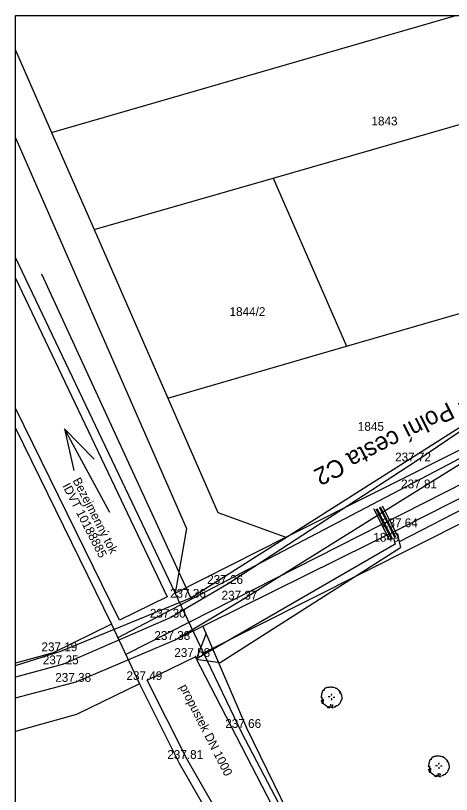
# Model space of a CAD drawing. Extents: x -601589 to -601440, y -1201842 to -1201527.
# Drawn here: x -601588.9 to -601539.2, y -1201615.4 to -1201526.7 of the extents above; entities that cross this region are included whole.
import ezdxf

# ---------------------------------------------------------------- set-up
doc = ezdxf.new("R2010")
doc.units = 0
for name, color, linetype in [('Definiční body', 7, 'Continuous'), ('Hranice parcel', 7, 'Continuous'), ('u_hrany', 7, 'Continuous'), ('u_osa', 7, 'Continuous'), ('u_popis', 7, 'Continuous'), ('u_příčný odvodňovací žlab', 7, 'Continuous'), ('u_terénní úpravy', 7, 'Continuous'), ('u_vysadba', 7, 'Continuous'), ('u_vyska', 7, 'Continuous'), ('x_rám', 7, 'Continuous')]:
    doc.layers.add(name, color=color, linetype=linetype)

msp = doc.modelspace()

# ---------------------------------------------------------------- linework, layer by layer
at = {"layer": 'Hranice parcel'}
for p, q in [((-601584.77, -1201539.96), (-601538.652, -1201526.653)), ((-601588.867, -1201530.599), (-601584.77, -1201539.96)), ((-601559.51, -1201545.16), (-601511.83, -1201531.46)), ((-601584.77, -1201539.96), (-601579.92, -1201551.03)), ((-601579.92, -1201551.03), (-601559.51, -1201545.16)), ((-601559.51, -1201545.16), (-601551.13, -1201564.33)), ((-601579.92, -1201551.03), (-601571.52, -1201570.23)), ((-601551.13, -1201564.33), (-601514.42, -1201553.71)), ((-601571.52, -1201570.23), (-601551.13, -1201564.33)), ((-601558.04, -1201586.08), (-601519.33, -1201566.6)), ((-601567.44, -1201599.25), (-601518.5, -1201574.62)), ((-601570.68, -1201592.44), (-601558.04, -1201586.08)), ((-601567.44, -1201599.25), (-601570.68, -1201592.44)), ((-601577.91, -1201595.98), (-601574.75, -1201602.78))]:
    msp.add_line(p, q, dxfattribs=at)
for points in [[(-601588.867, -1201540.58), (-601569.38, -1201585.08), (-601570.68, -1201592.44)], [(-601588.867, -1201554.262), (-601570.68, -1201592.44)], [(-601571.52, -1201570.23), (-601565.81, -1201583.28), (-601558.04, -1201586.08)], [(-601588.867, -1201573.638), (-601577.91, -1201595.98)], [(-601577.91, -1201595.98), (-601584.57, -1201599.24), (-601588.867, -1201600.418)], [(-601445.87, -1201723.83), (-601456.99, -1201723.59), (-601475.22, -1201720.69), (-601492.39, -1201715.61), (-601519.73, -1201684.8), (-601540.64, -1201651.14), (-601563.05, -1201608.38), (-601567.44, -1201599.25)], [(-601574.75, -1201602.78), (-601581.91, -1201606.29), (-601588.867, -1201608.194)], [(-601574.75, -1201602.78), (-601570.23, -1201611.8), (-601545.97, -1201654.03), (-601525.15, -1201688.8), (-601494.52, -1201722.78), (-601477.14, -1201727.24), (-601457.13, -1201731.39), (-601443.02, -1201731.69)]]:
    msp.add_lwpolyline(points, dxfattribs=at)
at = {"layer": 'u_hrany'}
for points in [[(-601517.05, -1201548.75), (-601518.98, -1201555.47), (-601521.95, -1201561.09), (-601526.18, -1201565.91), (-601543.22, -1201577.44), (-601564.63, -1201591.39), (-601571.15, -1201595.24), (-601583.39, -1201600.55), (-601588.867, -1201602.038)], [(-601568.87, -1201592.97), (-601585.89, -1201556.1)], [(-601588.867, -1201556.581), (-601571.58, -1201592.88), (-601577.01, -1201595.54), (-601588.867, -1201571.369)], [(-601583.7, -1201599.06), (-601568.87, -1201592.97), (-601526.18, -1201565.91)], [(-601588.867, -1201604.38), (-601581.97, -1201602.55), (-601570.67, -1201597.77), (-601563.01, -1201593.18), (-601542.69, -1201580.51), (-601524.37, -1201569.19), (-601517.89, -1201568.67), (-601514.2, -1201569.51), (-601511.31, -1201571.5), (-601509.75, -1201574.25)], [(-601570.67, -1201597.77), (-601544.7, -1201584.94), (-601517.03, -1201570.93)], [(-601567.51, -1201596.21), (-601562.55, -1201607.8), (-601549.33, -1201634.79), (-601540.29, -1201651.32), (-601519.62, -1201684.67)], [(-601588.867, -1201600.696), (-601583.7, -1201599.06)], [(-601573.85, -1201602.35), (-601568.4, -1201599.72), (-601541.51, -1201651.64)], [(-601545.11, -1201653.52), (-601569.35, -1201611.33), (-601573.85, -1201602.35)]]:
    msp.add_lwpolyline(points, dxfattribs=at)
at = {"layer": 'u_osa'}
msp.add_lwpolyline([(-601507.711, -1201526.653), (-601508.035, -1201556.382), (-601508.399, -1201559.4), (-601509.407, -1201562.268), (-601511.012, -1201564.849), (-601513.137, -1201567.023), (-601515.682, -1201568.685), (-601576.299, -1201599.446)], dxfattribs=at)
at = {"layer": 'u_popis'}
for p, q in [((-601578.133, -1201583.258), (-601583.273, -1201573.742)), ((-601583.273, -1201573.742), (-601582.207, -1201578.481)), ((-601583.273, -1201573.742), (-601579.913, -1201577.198))]:
    msp.add_line(p, q, dxfattribs=at)
at = {"layer": 'u_příčný odvodňovací žlab'}
for points in [[(-601545.609, -1201586.118), (-601546.515, -1201584.332), (-601547.353, -1201582.682)], [(-601545.52, -1201586.073), (-601546.426, -1201584.287), (-601547.263, -1201582.637)], [(-601545.297, -1201585.959), (-601546.203, -1201584.174), (-601547.041, -1201582.524)], [(-601546.216, -1201586.425), (-601547.122, -1201584.64), (-601548.027, -1201582.856)], [(-601545.993, -1201586.312), (-601546.899, -1201584.527), (-601547.736, -1201582.877)], [(-601545.904, -1201586.267), (-601546.81, -1201584.481), (-601547.647, -1201582.832)]]:
    msp.add_lwpolyline(points, dxfattribs=at)
at = {"layer": 'u_terénní úpravy'}
for p, q in [((-601545.756, -1201586.192), (-601545.593, -1201586.88)), ((-601545.297, -1201585.959), (-601544.993, -1201587.238)), ((-601567.152, -1201597.047), (-601568.274, -1201599.963)), ((-601568.271, -1201599.969), (-601565.539, -1201600.34))]:
    msp.add_line(p, q, dxfattribs=at)
for points in [[(-601511.197, -1201526.653), (-601511.285, -1201528.955), (-601511.232, -1201535.024), (-601513.147, -1201556.002), (-601514.131, -1201558.519), (-601515.245, -1201561.131), (-601516.655, -1201563.291), (-601517.726, -1201564.657), (-601519.33, -1201566.6), (-601521.678, -1201567.781), (-601538.799, -1201577.408), (-601577.284, -1201597.587)], [(-601510.358, -1201585.479), (-601510.939, -1201583.156), (-601511.905, -1201580.866), (-601513.234, -1201579.022), (-601515.173, -1201577.212), (-601516.815, -1201576.086), (-601517.621, -1201575.775), (-601519.795, -1201575.475), (-601521.737, -1201575.568), (-601523.807, -1201575.966), (-601536.406, -1201582.122), (-601545.145, -1201586.599)], [(-601545.593, -1201586.88), (-601568.271, -1201599.969)], [(-601565.539, -1201600.34), (-601544.993, -1201587.238)]]:
    msp.add_lwpolyline(points, dxfattribs=at)
at = {"layer": 'u_vysadba'}
for points in [[(-601553.83, -1201603.573), (-601553.829, -1201603.544), (-601553.769, -1201603.518), (-601553.739, -1201603.505), (-601553.709, -1201603.492), (-601553.679, -1201603.494), (-601553.65, -1201603.495), (-601553.663, -1201603.465), (-601553.676, -1201603.435), (-601553.659, -1201603.392), (-601553.643, -1201603.349), (-601553.611, -1201603.307), (-601553.58, -1201603.279), (-601553.55, -1201603.251), (-601553.504, -1201603.225), (-601553.46, -1201603.227), (-601553.43, -1201603.199), (-601553.355, -1201603.174), (-601553.296, -1201603.162), (-601553.251, -1201603.15), (-601553.193, -1201603.153), (-601553.148, -1201603.141), (-601553.105, -1201603.143), (-601553.032, -1201603.147), (-601552.958, -1201603.136), (-601552.885, -1201603.14), (-601552.797, -1201603.145), (-601552.71, -1201603.149), (-601552.637, -1201603.153), (-601552.593, -1201603.17), (-601552.565, -1201603.186)], [(-601552.418, -1201603.179), (-601552.434, -1201603.208), (-601552.436, -1201603.237), (-601552.452, -1201603.266), (-601552.408, -1201603.253), (-601552.378, -1201603.255), (-601552.349, -1201603.256), (-601552.306, -1201603.273), (-601552.262, -1201603.276), (-601552.22, -1201603.307), (-601552.192, -1201603.338), (-601552.165, -1201603.383), (-601552.123, -1201603.415), (-601552.067, -1201603.462), (-601552.026, -1201603.508), (-601551.998, -1201603.538), (-601551.957, -1201603.599), (-601551.9, -1201603.631), (-601551.858, -1201603.663), (-601551.815, -1201603.68), (-601551.817, -1201603.709)], [(-601553.83, -1201603.573), (-601553.831, -1201603.588), (-601553.877, -1201603.63), (-601553.908, -1201603.657), (-601553.91, -1201603.701), (-601553.912, -1201603.745), (-601553.915, -1201603.803), (-601553.932, -1201603.846), (-601553.949, -1201603.875), (-601553.965, -1201603.903), (-601553.982, -1201603.961), (-601553.984, -1201603.99), (-601553.987, -1201604.048), (-601553.989, -1201604.092), (-601553.991, -1201604.121), (-601554.009, -1201604.194), (-601554.026, -1201604.237), (-601554.029, -1201604.28), (-601554.045, -1201604.309), (-601554.032, -1201604.339), (-601553.989, -1201604.356), (-601553.899, -1201604.331), (-601553.869, -1201604.318), (-601553.902, -1201604.375), (-601553.932, -1201604.403), (-601553.949, -1201604.431), (-601553.951, -1201604.475), (-601553.922, -1201604.476), (-601553.878, -1201604.479), (-601553.865, -1201604.509), (-601553.882, -1201604.552), (-601553.898, -1201604.58), (-601553.9, -1201604.624), (-601553.903, -1201604.668)], [(-601552.831, -1201604.115), (-601552.82, -1201603.911)], [(-601551.817, -1201603.709), (-601551.861, -1201603.721), (-601551.906, -1201603.734), (-601551.922, -1201603.762), (-601551.909, -1201603.792), (-601551.882, -1201603.837), (-601551.852, -1201603.824), (-601551.807, -1201603.812), (-601551.78, -1201603.843), (-601551.767, -1201603.873), (-601551.768, -1201603.902), (-601551.742, -1201603.962), (-601551.73, -1201604.007), (-601551.718, -1201604.051), (-601551.691, -1201604.096), (-601551.692, -1201604.126), (-601551.694, -1201604.169), (-601551.696, -1201604.199), (-601551.684, -1201604.243), (-601551.672, -1201604.302), (-601551.675, -1201604.361), (-601551.664, -1201604.42), (-601551.665, -1201604.449), (-601551.667, -1201604.478), (-601551.669, -1201604.522), (-601551.7, -1201604.55), (-601551.701, -1201604.579), (-601551.718, -1201604.622), (-601551.735, -1201604.651), (-601551.781, -1201604.692), (-601551.784, -1201604.75), (-601551.801, -1201604.808), (-601551.82, -1201604.88), (-601551.867, -1201604.936), (-601551.9, -1201605.008), (-601551.932, -1201605.065), (-601551.992, -1201605.091), (-601552.023, -1201605.119), (-601552.069, -1201605.16), (-601552.1, -1201605.202), (-601552.117, -1201605.245), (-601552.177, -1201605.271), (-601552.222, -1201605.284), (-601552.252, -1201605.297), (-601552.295, -1201605.28), (-601552.338, -1201605.263), (-601552.355, -1201605.306), (-601552.373, -1201605.364), (-601552.389, -1201605.407), (-601552.434, -1201605.419), (-601552.478, -1201605.417)], [(-601554.034, -1201604.661), (-601554.021, -1201604.691), (-601554.009, -1201604.735), (-601553.996, -1201604.765), (-601553.997, -1201604.795), (-601553.969, -1201604.811), (-601553.938, -1201604.783), (-601553.892, -1201604.742), (-601553.921, -1201604.74), (-601553.963, -1201604.709), (-601554.006, -1201604.692)], [(-601553.944, -1201604.9), (-601553.934, -1201604.988), (-601553.89, -1201604.991), (-601553.861, -1201604.992), (-601553.817, -1201604.98), (-601553.874, -1201604.962), (-601553.918, -1201604.96), (-601553.931, -1201604.93)], [(-601553.876, -1201604.728), (-601553.835, -1201604.774), (-601553.793, -1201604.82), (-601553.751, -1201604.852)], [(-601553.751, -1201604.852), (-601553.78, -1201604.85), (-601553.81, -1201604.848), (-601553.839, -1201604.847), (-601553.852, -1201604.817), (-601553.85, -1201604.788), (-601553.863, -1201604.758)], [(-601553.852, -1201604.539), (-601553.854, -1201604.583), (-601553.841, -1201604.613), (-601553.829, -1201604.657), (-601553.816, -1201604.687), (-601553.787, -1201604.689), (-601553.77, -1201604.66), (-601553.71, -1201604.634), (-601553.753, -1201604.617), (-601553.782, -1201604.601), (-601553.839, -1201604.569)], [(-601553.38, -1201605.31), (-601553.423, -1201605.294), (-601553.452, -1201605.277), (-601553.481, -1201605.276), (-601553.508, -1201605.23), (-601553.536, -1201605.214), (-601553.578, -1201605.183), (-601553.621, -1201605.166), (-601553.663, -1201605.12), (-601553.691, -1201605.089), (-601553.762, -1201605.056), (-601553.76, -1201605.012), (-601553.757, -1201604.968), (-601553.77, -1201604.938), (-601553.799, -1201604.922), (-601553.767, -1201604.88), (-601553.738, -1201604.882)], [(-601553.014, -1201604.266), (-601553.219, -1201604.256)], [(-601552.847, -1201604.422), (-601552.858, -1201604.626)], [(-601552.664, -1201604.285), (-601552.459, -1201604.281)], [(-601553.369, -1201605.37), (-601553.273, -1201605.492), (-601553.246, -1201605.537), (-601553.214, -1201605.495), (-601553.213, -1201605.466), (-601553.241, -1201605.45), (-601553.284, -1201605.433), (-601553.312, -1201605.416), (-601553.341, -1201605.4)], [(-601553.146, -1201605.323), (-601553.15, -1201605.396), (-601553.138, -1201605.44), (-601553.11, -1201605.471), (-601553.051, -1201605.46), (-601553.02, -1201605.432), (-601553.034, -1201605.402), (-601553.077, -1201605.385), (-601553.12, -1201605.368)], [(-601552.976, -1201605.141), (-601552.965, -1201605.215), (-601552.938, -1201605.261), (-601552.894, -1201605.248), (-601552.892, -1201605.219), (-601552.891, -1201605.19), (-601552.934, -1201605.173), (-601552.962, -1201605.157)], [(-601552.941, -1201605.319), (-601552.858, -1201605.397), (-601552.829, -1201605.413), (-601552.816, -1201605.443), (-601552.847, -1201605.47), (-601552.876, -1201605.469), (-601552.889, -1201605.439), (-601552.916, -1201605.394), (-601552.944, -1201605.363)], [(-601552.773, -1201605.181), (-601552.747, -1201605.241), (-601552.735, -1201605.286), (-601552.707, -1201605.317), (-601552.677, -1201605.304), (-601552.645, -1201605.261), (-601552.644, -1201605.232), (-601552.688, -1201605.23), (-601552.716, -1201605.214), (-601552.745, -1201605.198), (-601552.774, -1201605.196)], [(-601552.742, -1201605.432), (-601552.732, -1201605.506), (-601552.718, -1201605.536), (-601552.688, -1201605.523), (-601552.657, -1201605.48), (-601552.685, -1201605.45), (-601552.713, -1201605.434), (-601552.742, -1201605.432)], [(-601552.478, -1201605.417), (-601552.522, -1201605.429), (-601552.553, -1201605.457)], [(-601541.592, -1201611.426), (-601541.591, -1201611.397), (-601541.531, -1201611.371), (-601541.501, -1201611.358), (-601541.471, -1201611.345), (-601541.441, -1201611.346), (-601541.412, -1201611.348), (-601541.425, -1201611.318), (-601541.438, -1201611.288), (-601541.421, -1201611.245), (-601541.405, -1201611.202), (-601541.373, -1201611.159), (-601541.342, -1201611.132), (-601541.312, -1201611.104), (-601541.266, -1201611.077), (-601541.222, -1201611.08), (-601541.192, -1201611.052), (-601541.117, -1201611.027), (-601541.058, -1201611.015), (-601541.013, -1201611.003), (-601540.955, -1201611.006), (-601540.91, -1201610.994), (-601540.867, -1201610.996), (-601540.794, -1201611), (-601540.72, -1201610.989), (-601540.647, -1201610.993), (-601540.559, -1201610.997), (-601540.472, -1201611.002), (-601540.399, -1201611.006), (-601540.355, -1201611.023), (-601540.327, -1201611.039)], [(-601540.18, -1201611.032), (-601540.196, -1201611.061), (-601540.198, -1201611.09), (-601540.214, -1201611.118), (-601540.17, -1201611.106), (-601540.14, -1201611.107), (-601540.111, -1201611.109), (-601540.068, -1201611.126), (-601540.024, -1201611.128), (-601539.982, -1201611.16), (-601539.954, -1201611.191), (-601539.927, -1201611.236), (-601539.885, -1201611.267), (-601539.829, -1201611.314), (-601539.788, -1201611.36), (-601539.76, -1201611.391), (-601539.719, -1201611.452), (-601539.662, -1201611.484), (-601539.62, -1201611.516), (-601539.577, -1201611.533), (-601539.579, -1201611.562)], [(-601541.592, -1201611.426), (-601541.593, -1201611.441), (-601541.639, -1201611.482), (-601541.67, -1201611.51), (-601541.672, -1201611.554), (-601541.674, -1201611.597), (-601541.677, -1201611.656), (-601541.694, -1201611.699), (-601541.711, -1201611.727), (-601541.727, -1201611.756), (-601541.744, -1201611.813), (-601541.746, -1201611.843), (-601541.749, -1201611.901), (-601541.751, -1201611.945), (-601541.753, -1201611.974), (-601541.771, -1201612.046), (-601541.788, -1201612.089), (-601541.791, -1201612.133), (-601541.807, -1201612.162), (-601541.794, -1201612.192), (-601541.751, -1201612.208), (-601541.661, -1201612.184), (-601541.631, -1201612.171), (-601541.664, -1201612.228), (-601541.694, -1201612.255), (-601541.711, -1201612.284), (-601541.713, -1201612.328), (-601541.684, -1201612.329), (-601541.64, -1201612.331), (-601541.627, -1201612.361), (-601541.644, -1201612.404), (-601541.66, -1201612.433), (-601541.662, -1201612.477), (-601541.665, -1201612.52)], [(-601540.593, -1201611.968), (-601540.582, -1201611.763)], [(-601539.579, -1201611.562), (-601539.623, -1201611.574), (-601539.668, -1201611.586), (-601539.684, -1201611.615), (-601539.671, -1201611.645), (-601539.644, -1201611.69), (-601539.614, -1201611.677), (-601539.569, -1201611.665), (-601539.542, -1201611.696), (-601539.529, -1201611.725), (-601539.53, -1201611.755), (-601539.504, -1201611.815), (-601539.492, -1201611.859), (-601539.48, -1201611.904), (-601539.453, -1201611.949), (-601539.454, -1201611.978), (-601539.456, -1201612.022), (-601539.458, -1201612.051), (-601539.446, -1201612.096), (-601539.434, -1201612.155), (-601539.437, -1201612.214), (-601539.426, -1201612.273), (-601539.427, -1201612.302), (-601539.429, -1201612.331), (-601539.431, -1201612.375), (-601539.462, -1201612.403), (-601539.463, -1201612.432), (-601539.48, -1201612.475), (-601539.497, -1201612.503), (-601539.543, -1201612.545), (-601539.546, -1201612.603), (-601539.563, -1201612.661), (-601539.582, -1201612.733), (-601539.629, -1201612.789), (-601539.662, -1201612.861), (-601539.694, -1201612.917), (-601539.754, -1201612.944), (-601539.785, -1201612.971), (-601539.831, -1201613.013), (-601539.862, -1201613.055), (-601539.879, -1201613.098), (-601539.939, -1201613.124), (-601539.984, -1201613.136), (-601540.014, -1201613.149), (-601540.057, -1201613.133), (-601540.1, -1201613.116), (-601540.117, -1201613.159), (-601540.135, -1201613.216), (-601540.151, -1201613.259), (-601540.196, -1201613.272), (-601540.24, -1201613.269)], [(-601541.796, -1201612.514), (-601541.783, -1201612.544), (-601541.771, -1201612.588), (-601541.758, -1201612.618), (-601541.759, -1201612.647), (-601541.731, -1201612.663), (-601541.7, -1201612.636), (-601541.654, -1201612.594), (-601541.683, -1201612.593), (-601541.725, -1201612.561), (-601541.768, -1201612.544)], [(-601541.706, -1201612.753), (-601541.696, -1201612.841), (-601541.652, -1201612.843), (-601541.623, -1201612.845), (-601541.579, -1201612.833), (-601541.636, -1201612.815), (-601541.68, -1201612.813), (-601541.693, -1201612.783)], [(-601541.638, -1201612.58), (-601541.597, -1201612.627), (-601541.555, -1201612.673), (-601541.513, -1201612.704)], [(-601541.513, -1201612.704), (-601541.542, -1201612.703), (-601541.572, -1201612.701), (-601541.601, -1201612.7), (-601541.614, -1201612.67), (-601541.612, -1201612.64), (-601541.625, -1201612.61)], [(-601541.614, -1201612.391), (-601541.616, -1201612.435), (-601541.603, -1201612.465), (-601541.591, -1201612.51), (-601541.578, -1201612.54), (-601541.549, -1201612.541), (-601541.532, -1201612.513), (-601541.472, -1201612.487), (-601541.515, -1201612.47), (-601541.544, -1201612.454), (-601541.601, -1201612.421)], [(-601541.142, -1201613.163), (-601541.185, -1201613.146), (-601541.214, -1201613.13), (-601541.243, -1201613.128), (-601541.27, -1201613.083), (-601541.298, -1201613.067), (-601541.34, -1201613.035), (-601541.383, -1201613.019), (-601541.425, -1201612.972), (-601541.453, -1201612.942), (-601541.524, -1201612.909), (-601541.522, -1201612.865), (-601541.519, -1201612.821), (-601541.532, -1201612.791), (-601541.561, -1201612.775), (-601541.529, -1201612.733), (-601541.5, -1201612.734)], [(-601540.776, -1201612.119), (-601540.981, -1201612.108)], [(-601540.609, -1201612.274), (-601540.62, -1201612.479)], [(-601540.426, -1201612.138), (-601540.221, -1201612.134)], [(-601541.131, -1201613.222), (-601541.035, -1201613.344), (-601541.008, -1201613.39), (-601540.976, -1201613.348), (-601540.975, -1201613.318), (-601541.003, -1201613.302), (-601541.046, -1201613.285), (-601541.074, -1201613.269), (-601541.103, -1201613.253)], [(-601540.908, -1201613.175), (-601540.912, -1201613.248), (-601540.9, -1201613.293), (-601540.872, -1201613.324), (-601540.813, -1201613.312), (-601540.782, -1201613.285), (-601540.796, -1201613.255), (-601540.839, -1201613.238), (-601540.882, -1201613.221)], [(-601540.738, -1201612.994), (-601540.727, -1201613.068), (-601540.7, -1201613.113), (-601540.656, -1201613.101), (-601540.654, -1201613.072), (-601540.653, -1201613.043), (-601540.696, -1201613.026), (-601540.724, -1201613.009)], [(-601540.703, -1201613.172), (-601540.62, -1201613.249), (-601540.591, -1201613.265), (-601540.578, -1201613.295), (-601540.609, -1201613.323), (-601540.638, -1201613.321), (-601540.651, -1201613.292), (-601540.678, -1201613.246), (-601540.706, -1201613.215)], [(-601540.535, -1201613.034), (-601540.509, -1201613.094), (-601540.497, -1201613.139), (-601540.469, -1201613.169), (-601540.439, -1201613.156), (-601540.407, -1201613.114), (-601540.406, -1201613.085), (-601540.45, -1201613.083), (-601540.478, -1201613.066), (-601540.507, -1201613.05), (-601540.536, -1201613.049)], [(-601540.504, -1201613.285), (-601540.494, -1201613.358), (-601540.48, -1201613.388), (-601540.45, -1201613.375), (-601540.419, -1201613.333), (-601540.447, -1201613.302), (-601540.475, -1201613.286), (-601540.504, -1201613.285)], [(-601540.24, -1201613.269), (-601540.284, -1201613.282), (-601540.315, -1201613.309)]]:
    msp.add_lwpolyline(points, dxfattribs=at)
at = {"layer": 'x_rám'}
msp.add_lwpolyline([(-601440.367, -1201526.653), (-601440.367, -1201841.653), (-601588.867, -1201841.653), (-601588.867, -1201526.653)], close=True, dxfattribs=at)

# ---------------------------------------------------------------- texts
at = {"layer": 'Definiční body'}
for s, p in [('1843', (-601548.29, -1201539.166)), ('1844/2', (-601564.47, -1201560.876)), ('1845', (-601549.84, -1201573.956)), ('1849', (-601548.07, -1201586.586))]:
    msp.add_text(s, height=1, dxfattribs=at).set_placement(p)
at = {"layer": 'u_popis'}
for s, height, rotation, p in [('SO 101- Polní cesta C2', 2, 206.90572, (-601529.971, -1201565.781)), ('Bezejmenný tok', 1, 297.239, (-601582.384, -1201579.602)), ('IDVT 10188885', 1, 297.239, (-601583.567, -1201580.211)), ('propustek DN 1000', 1, 296.90572, (-601570.19, -1201603.123))]:
    msp.add_text(s, height=height, rotation=rotation, dxfattribs=at).set_placement(p)
at = {"layer": 'u_vyska'}
for s, p in [('237.72', (-601545.591, -1201577.44)), ('237.81', (-601544.908, -1201580.51)), ('237.64', (-601547.093, -1201584.94)), ('237.26', (-601567.019, -1201591.39)), ('237.36', (-601571.259, -1201592.97)), ('237.37', (-601565.381, -1201593.18)), ('237.30', (-601573.556, -1201595.24)), ('237.38', (-601573.04, -1201597.77)), ('237.19', (-601585.915, -1201599.06)), ('237.58', (-601570.77, -1201599.72)), ('237.25', (-601585.76, -1201600.55)), ('237.49', (-601576.224, -1201602.35)), ('237.38', (-601584.34, -1201602.55)), ('237.66', (-601564.958, -1201607.8)), ('237.81', (-601571.568, -1201611.33))]:
    msp.add_text(s, height=1, dxfattribs=at).set_placement(p)

doc.saveas('drawing.dxf')
